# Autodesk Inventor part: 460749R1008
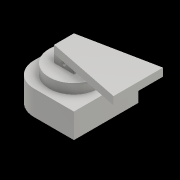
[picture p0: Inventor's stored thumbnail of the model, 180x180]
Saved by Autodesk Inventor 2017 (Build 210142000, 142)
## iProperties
Created: 2016-07
Part Number: 460749R1008
Material: Aluminum 6061
Document SubType Name: Modeling
Designer: Polytech
Mass: 1260.26 g
Surface Area: 611.154 cm^2
Volume: 466.762 cm^3
Density: 2.7 g/cm^3
Appearance: Aluminum - Flat
Author: Polytech
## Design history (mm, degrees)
sketch "Sketch1"
  geometry: C1 r 23 at (0, 0); 1 further point
  constraints: 1 centre point, 1 coincident
  dimensions: "d0" = 46 diameter of C1
extrude "Extrusion1" new body sketch "Sketch1" distance "d1" = 18; taper "d2" = 0 deg
sketch "Sketch2"
  geometry: L1 (-11.75, -48.75)-(48.75, -48.75); L2 (48.75, -48.75)-(48.75, 48.75); L3 (48.75, 48.75)-(-11.75, 48.75); L4 (-48.75, 11.75)-(-48.75, -11.75); L5 (-48.75, -48.75)-(48.75, 48.75); L6 (48.75, -48.75)-(-48.75, 48.75); A1 r 37 centre (-11.75, 11.75) between (-11.75, 48.75) and (-48.75, 11.75); A2 r 37 centre (-11.75, -11.75) between (-48.75, -11.75) and (-11.75, -48.75); 1 further point
  constraints: 12 end point, 4 point on circle, 4 point on line, 4 tangent, 2 centre point, 2 midpoint, 2 parallel, 1 equal radius, 1 horizontal, 1 perpendicular
  dimensions: "d3" = 97.5 distance of L6.end L2.end; "d4" = 97.5 distance of L2.end L1.end; "d5" = 37 radius of A1
extrude "Extrusion2" join sketch "Sketch2" distance "d6" = 37.5; taper "d7" = 0 deg
sketch "Sketch3"
  geometry: C1 r 37.5 at (0, 0); 1 further point
  constraints: 1 centre point, 1 coincident
  dimensions: "d8" = 75 diameter of C1
extrude "Extrusion3" join sketch "Sketch3" distance "d9" = 15; taper "d10" = 0 deg
sketch "Sketch4"
  geometry: L1 (-15, -15)-(15, -15); L2 (15, -15)-(15, 15); L3 (15, 15)-(-15, 15); L4 (-15, 15)-(-15, -15); L5 (-15, -15)-(15, 15); L6 (15, -15)-(-15, 15); 1 further point
  constraints: 12 end point, 2 midpoint, 2 parallel, 1 horizontal, 1 perpendicular
  dimensions: "d11" = 30 distance of L3.end L2.end; "d12" = 30 distance of L2.end L1.end
extrude "Extrusion4" join sketch "Sketch4" distance "d13" = 12; taper "d14" = 0 deg
sketch "Sketch5"
  geometry: L1 (-15, -6)-(15, -6); L2 (15, -6)-(15, 6); L3 (15, 6)-(-15, 6); L4 (-15, 6)-(-15, -6); L5 (-15, -6)-(15, 6); L6 (15, -6)-(-15, 6); 1 further point
  constraints: 12 end point, 2 midpoint, 2 parallel, 1 horizontal, 1 perpendicular
  dimensions: "d15" = 30 distance of L3.end L2.end; "d16" = 12 distance of L2.end L1.end
extrude "Extrusion5" cut sketch "Sketch5" distance "d17" = 12; taper "d18" = 0 deg
sketch "Sketch6"
  geometry: L1 (52.5, 0)-(-22.5, 0) reference; C1 r 3 at (15, 6); 1 further point
  constraints: 1 centre point, 1 vertical alignment
  dimensions: "d19" = 3 radius of C1; "d20" = 6 distance from line of L1 C1.centre
extrude "Extrusion6" cut sketch "Sketch6" stored distance "d21" = 12; taper "d22" = 0 deg
sketch "Sketch7"
  geometry: L1 (-15, 15)-(-15, -15); L2 (-15, -15)-(97.5, -37.5); L3 (97.5, -37.5)-(97.5, 37.5); L4 (97.5, 37.5)-(-15, 15); 4 further points
  constraints: 8 end point, 2 coincident, 1 horizontal alignment, 1 midpoint, 1 parallel, 1 vertical
  dimensions: "d23" = 30 distance of L1.start L1.end (derived); "d24" = 75 distance of L2.end L3.end; "d25" = 97.5 horizontal distance of L2.end point (0, 0)
extrude "Extrusion7" join sketch "Sketch7" distance "d26" = 12; taper "d27" = 0 deg
sketch "Sketch8"
  geometry: C1 r 23 at (0, 0); 1 further point
  constraints: 1 centre point, 1 coincident
  dimensions: "d28" = 46 diameter of C1
extrude "Extrusion8" cut sketch "Sketch8" distance "d29" = 24.5; taper "d30" = 0 deg
body "Solid1"
